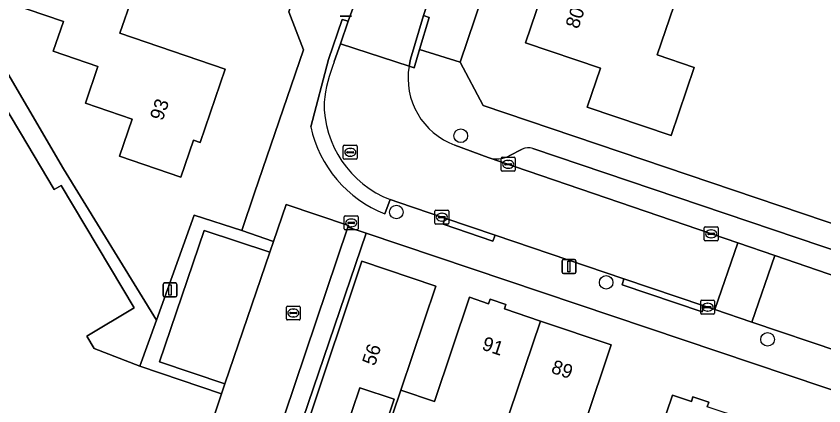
# Model space of a CAD drawing. Extents: x 157767 to 159172, y 387839 to 389425.
# Drawn here: x 158190.5 to 158248.5, y 388348.6 to 388376.5 of the extents above; entities that cross this region are included whole.
import ezdxf

# ---------------------------------------------------------------- set-up
doc = ezdxf.new("R2010")
doc.units = 0
for name, color, linetype in [('IMGEO_Boom', 7, 'Continuous'), ('IMGEO_Brandkraan', 7, 'Continuous'), ('IMGEO_Erf', 7, 'Continuous'), ('IMGEO_Kolk', 7, 'Continuous'), ('IMGEO_Lichtmast', 7, 'Continuous'), ('IMGEO_Pand', 7, 'Continuous'), ('IMGEO_Pand_nummerreeks', 7, 'Continuous'), ('IMGEO_Parkeervlak_open', 7, 'Continuous'), ('IMGEO_Rijbaan_lokaal_open', 7, 'Continuous'), ('IMGEO_Rioolput', 7, 'Continuous'), ('IMGEO_Voetpad_open', 7, 'Continuous')]:
    doc.layers.add(name, color=color, linetype=linetype)

msp = doc.modelspace()

# ---------------------------------------------------------------- linework, layer by layer
at = {"layer": 'IMGEO_Boom'}
for centre in [(158222.451, 388367.952), (158217.826, 388362.477), (158232.884, 388357.425), (158244.465, 388353.331)]:
    msp.add_circle(centre, 0.489, dxfattribs=at)
at = {"layer": 'IMGEO_Brandkraan'}
for p, q in [((158214.085, 388361.271), (158214.085, 388362.123)), ((158214.16, 388362.197), (158215.012, 388362.197)), ((158215.086, 388362.123), (158215.086, 388361.271)), ((158214.344, 388361.691), (158214.344, 388361.703)), ((158214.782, 388361.654), (158214.384, 388361.654)), ((158214.387, 388361.74), (158214.785, 388361.74)), ((158214.573, 388361.977), (158214.598, 388361.977)), ((158214.828, 388361.703), (158214.828, 388361.691)), ((158215.012, 388361.197), (158214.16, 388361.197)), ((158214.596, 388361.417), (158214.571, 388361.417))]:
    msp.add_line(p, q, dxfattribs=at)
for points in [[(158214.085, 388361.271), (158214.085, 388362.123)], [(158214.16, 388362.197), (158215.012, 388362.197)], [(158215.086, 388362.123), (158215.086, 388361.271)], [(158215.012, 388361.197), (158214.16, 388361.197)]]:
    msp.add_lwpolyline(points, dxfattribs=at)
for centre, radius, start, end in [((158214.162, 388362.121), 0.0765, 91.55205, 178.44795), ((158214.162, 388362.121), 0.0765, 91.55205, 178.44795), ((158215.01, 388362.121), 0.0765, 1.55205, 88.44795), ((158215.01, 388362.121), 0.0765, 1.55205, 88.44795), ((158214.384, 388361.7), 0.0403, 85.87752, 175.75265), ((158214.381, 388361.69), 0.0366, 178.93798, 274.71019), ((158214.785, 388361.697), 0.043, 264.86636, 352.45326), ((158214.789, 388361.702), 0.0386, 1.73085, 96.63898), ((158214.162, 388361.273), 0.0765, 181.55205, 268.44795), ((158214.162, 388361.273), 0.0765, 181.55205, 268.44795), ((158215.01, 388361.273), 0.0765, 271.55205, 358.44795), ((158215.01, 388361.273), 0.0765, 271.55205, 358.44795)]:
    msp.add_arc(centre, radius, start, end, dxfattribs=at)
for centre, major_axis, ratio, start_param, end_param in [((158214.572, 388361.697), (-0.387, 0.002), 0.722429, 4.712389, 7.853982), ((158214.597, 388361.697), (-0.39, 0.002), 0.717154, 1.570796, 4.712389)]:
    msp.add_ellipse(centre, major_axis=major_axis, ratio=ratio, start_param=start_param, end_param=end_param, dxfattribs=at)
at = {"layer": 'IMGEO_Erf'}
for points in [[(158227.437, 388427.591), (158206.398, 388461.811), (158193.554, 388453.846), (158183.168, 388447.406), (158182.041, 388442.936), (158182.177, 388442.783), (158184.992, 388444.506), (158185.402, 388443.835), (158188.66, 388445.829), (158190.411, 388442.966), (158187.153, 388440.973), (158188.112, 388439.406), (158185.297, 388437.683), (158197.216, 388418.782), (158193.835, 388409.215), (158175.068, 388397.881), (158178.573, 388391.881), (158193.933, 388365.581), (158200.612, 388354.718), (158203.311, 388362.254), (158206.731, 388361.142), (158207.656, 388363.849), (158211.167, 388374.122), (158210.098, 388376.863)], [(158312.755, 388341.098), (158312.502, 388341.518), (158306.661, 388351.075), (158298.895, 388363.783), (158266.215, 388343.931), (158215.655, 388360.952), (158211.11, 388347.607), (158210.283, 388345.18), (158209.386, 388342.547), (158208.654, 388340.397), (158214.388, 388338.441), (158213.37, 388335.454), (158271.151, 388315.645)]]:
    msp.add_lwpolyline(points, close=True, dxfattribs=at)
for points in [[(158254.733, 388410.921), (158237.149, 388416.834), (158222.397, 388373.231), (158224.063, 388370.135), (158264.935, 388356.284)], [(158204.506, 388347.12), (158205.279, 388349.421), (158199.422, 388351.396), (158196.126, 388352.68), (158195.601, 388353.556), (158199.017, 388355.601), (158193.759, 388364.381), (158193.273, 388364.089), (158190.849, 388368.154), (158181.209, 388384.323)], [(158237.737, 388377.264), (158236.555, 388373.757), (158239.207, 388372.863), (158237.559, 388367.975), (158231.529, 388370.008), (158232.477, 388372.819), (158227.1, 388374.631), (158228.983, 388380.218)], [(158198.86, 388377.879), (158197.988, 388375.331), (158205.547, 388372.742), (158203.744, 388367.476), (158203.257, 388367.643), (158202.348, 388364.986), (158197.958, 388366.489), (158198.867, 388369.145), (158195.504, 388370.297), (158196.408, 388372.938), (158193.199, 388374.037), (158193.928, 388376.164), (158191.323, 388377.056)], [(158211.509, 388347.473), (158215.359, 388358.94), (158220.658, 388357.16), (158218.15, 388349.69), (158220.57, 388348.878), (158223.081, 388356.354), (158224.447, 388355.896), (158224.556, 388356.219), (158225.685, 388355.841), (158225.576, 388355.518), (158228.16, 388354.65), (158233.239, 388352.943), (158231.317, 388347.218)], [(158215.704, 388343.169), (158217.674, 388349.034), (158215.209, 388349.862), (158214.113, 388346.599)], [(158236.359, 388345.525), (158237.638, 388349.335), (158239.004, 388348.877), (158239.113, 388349.2), (158240.242, 388348.822), (158240.132, 388348.497)]]:
    msp.add_lwpolyline(points, dxfattribs=at)
at = {"layer": 'IMGEO_Kolk'}
for p, q in [((158225.349, 388365.48), (158225.349, 388366.332)), ((158225.424, 388366.406), (158226.276, 388366.406)), ((158225.837, 388366.186), (158225.862, 388366.186)), ((158226.35, 388366.332), (158226.35, 388365.48)), ((158225.608, 388365.9), (158225.608, 388365.912)), ((158226.046, 388365.863), (158225.648, 388365.863)), ((158225.651, 388365.949), (158226.049, 388365.949)), ((158225.86, 388365.626), (158225.835, 388365.626)), ((158226.092, 388365.912), (158226.092, 388365.9)), ((158226.276, 388365.406), (158225.424, 388365.406)), ((158220.593, 388361.68), (158220.593, 388362.532)), ((158220.668, 388362.606), (158221.52, 388362.606)), ((158220.852, 388362.1), (158220.852, 388362.112)), ((158220.895, 388362.149), (158221.293, 388362.149)), ((158221.081, 388362.386), (158221.106, 388362.386)), ((158221.336, 388362.112), (158221.336, 388362.1)), ((158221.594, 388362.532), (158221.594, 388361.68)), ((158221.52, 388361.606), (158220.668, 388361.606)), ((158221.29, 388362.063), (158220.892, 388362.063)), ((158221.104, 388361.826), (158221.079, 388361.826)), ((158239.917, 388360.487), (158239.917, 388361.339)), ((158239.992, 388361.413), (158240.844, 388361.413)), ((158240.176, 388360.907), (158240.176, 388360.919)), ((158240.219, 388360.956), (158240.617, 388360.956)), ((158240.405, 388361.193), (158240.43, 388361.193)), ((158240.66, 388360.919), (158240.66, 388360.907)), ((158240.918, 388361.339), (158240.918, 388360.487)), ((158240.844, 388360.413), (158239.992, 388360.413)), ((158240.614, 388360.87), (158240.216, 388360.87)), ((158240.428, 388360.633), (158240.403, 388360.633)), ((158210.005, 388355.724), (158210.857, 388355.724)), ((158239.666, 388355.217), (158239.666, 388356.069)), ((158239.741, 388356.143), (158240.593, 388356.143)), ((158240.154, 388355.923), (158240.179, 388355.923)), ((158240.667, 388356.069), (158240.667, 388355.217)), ((158209.93, 388354.798), (158209.93, 388355.65)), ((158210.189, 388355.218), (158210.189, 388355.23)), ((158210.627, 388355.181), (158210.229, 388355.181)), ((158210.232, 388355.267), (158210.63, 388355.267)), ((158210.418, 388355.504), (158210.443, 388355.504)), ((158210.673, 388355.23), (158210.673, 388355.218)), ((158210.931, 388355.65), (158210.931, 388354.798)), ((158240.593, 388355.143), (158239.741, 388355.143)), ((158239.925, 388355.637), (158239.925, 388355.649)), ((158240.363, 388355.6), (158239.965, 388355.6)), ((158239.968, 388355.686), (158240.366, 388355.686)), ((158240.177, 388355.363), (158240.152, 388355.363)), ((158240.409, 388355.649), (158240.409, 388355.637)), ((158210.857, 388354.724), (158210.005, 388354.724)), ((158210.441, 388354.944), (158210.416, 388354.944))]:
    msp.add_line(p, q, dxfattribs=at)
for points in [[(158225.349, 388365.48), (158225.349, 388366.332)], [(158225.424, 388366.406), (158226.276, 388366.406)], [(158226.35, 388366.332), (158226.35, 388365.48)], [(158226.276, 388365.406), (158225.424, 388365.406)], [(158220.593, 388361.68), (158220.593, 388362.532)], [(158220.668, 388362.606), (158221.52, 388362.606)], [(158221.594, 388362.532), (158221.594, 388361.68)], [(158221.52, 388361.606), (158220.668, 388361.606)], [(158239.917, 388360.487), (158239.917, 388361.339)], [(158239.992, 388361.413), (158240.844, 388361.413)], [(158240.918, 388361.339), (158240.918, 388360.487)], [(158240.844, 388360.413), (158239.992, 388360.413)], [(158210.005, 388355.724), (158210.857, 388355.724)], [(158239.666, 388355.217), (158239.666, 388356.069)], [(158239.741, 388356.143), (158240.593, 388356.143)], [(158240.667, 388356.069), (158240.667, 388355.217)], [(158209.93, 388354.798), (158209.93, 388355.65)], [(158210.931, 388355.65), (158210.931, 388354.798)], [(158240.593, 388355.143), (158239.741, 388355.143)], [(158210.857, 388354.724), (158210.005, 388354.724)]]:
    msp.add_lwpolyline(points, dxfattribs=at)
for centre, radius, start, end in [((158225.426, 388366.33), 0.0765, 91.55205, 178.44795), ((158225.426, 388366.33), 0.0765, 91.55205, 178.44795), ((158226.274, 388366.33), 0.0765, 1.55205, 88.44795), ((158226.274, 388366.33), 0.0765, 1.55205, 88.44795), ((158225.648, 388365.909), 0.0403, 85.87752, 175.75265), ((158225.645, 388365.899), 0.0366, 178.93798, 274.71019), ((158226.049, 388365.906), 0.043, 264.86636, 352.45326), ((158226.053, 388365.911), 0.0386, 1.73085, 96.63898), ((158225.426, 388365.482), 0.0765, 181.55205, 268.44795), ((158225.426, 388365.482), 0.0765, 181.55205, 268.44795), ((158226.274, 388365.482), 0.0765, 271.55205, 358.44795), ((158226.274, 388365.482), 0.0765, 271.55205, 358.44795), ((158220.67, 388362.53), 0.0765, 91.55205, 178.44795), ((158220.67, 388362.53), 0.0765, 91.55205, 178.44795), ((158220.892, 388362.109), 0.0403, 85.87752, 175.75265), ((158220.889, 388362.099), 0.0366, 178.93798, 274.71019), ((158221.293, 388362.106), 0.043, 264.86636, 352.45326), ((158221.297, 388362.111), 0.0386, 1.73085, 96.63898), ((158221.518, 388362.53), 0.0765, 1.55205, 88.44795), ((158221.518, 388362.53), 0.0765, 1.55205, 88.44795), ((158220.67, 388361.682), 0.0765, 181.55205, 268.44795), ((158220.67, 388361.682), 0.0765, 181.55205, 268.44795), ((158221.518, 388361.682), 0.0765, 271.55205, 358.44795), ((158221.518, 388361.682), 0.0765, 271.55205, 358.44795), ((158239.994, 388361.337), 0.0765, 91.55205, 178.44795), ((158239.994, 388361.337), 0.0765, 91.55205, 178.44795), ((158240.216, 388360.916), 0.0403, 85.87752, 175.75265), ((158240.621, 388360.918), 0.0386, 1.73085, 96.63898), ((158240.842, 388361.337), 0.0765, 1.55205, 88.44795), ((158240.842, 388361.337), 0.0765, 1.55205, 88.44795), ((158239.994, 388360.489), 0.0765, 181.55205, 268.44795), ((158239.994, 388360.489), 0.0765, 181.55205, 268.44795), ((158240.213, 388360.906), 0.0366, 178.93798, 274.71019), ((158240.617, 388360.913), 0.043, 264.86636, 352.45326), ((158240.842, 388360.489), 0.0765, 271.55205, 358.44795), ((158240.842, 388360.489), 0.0765, 271.55205, 358.44795), ((158210.007, 388355.648), 0.0765, 91.55205, 178.44795), ((158210.007, 388355.648), 0.0765, 91.55205, 178.44795), ((158210.855, 388355.648), 0.0765, 1.55205, 88.44795), ((158210.855, 388355.648), 0.0765, 1.55205, 88.44795), ((158239.743, 388356.067), 0.0765, 91.55205, 178.44795), ((158239.743, 388356.067), 0.0765, 91.55205, 178.44795), ((158240.591, 388356.067), 0.0765, 1.55205, 88.44795), ((158240.591, 388356.067), 0.0765, 1.55205, 88.44795), ((158210.229, 388355.227), 0.0403, 85.87752, 175.75265), ((158210.226, 388355.217), 0.0366, 178.93798, 274.71019), ((158210.63, 388355.224), 0.043, 264.86636, 352.45326), ((158210.634, 388355.229), 0.0386, 1.73085, 96.63898), ((158239.743, 388355.219), 0.0765, 181.55205, 268.44795), ((158239.743, 388355.219), 0.0765, 181.55205, 268.44795), ((158239.965, 388355.646), 0.0403, 85.87752, 175.75265), ((158239.962, 388355.636), 0.0366, 178.93798, 274.71019), ((158240.366, 388355.643), 0.043, 264.86636, 352.45326), ((158240.37, 388355.648), 0.0386, 1.73085, 96.63898), ((158240.591, 388355.219), 0.0765, 271.55205, 358.44795), ((158240.591, 388355.219), 0.0765, 271.55205, 358.44795), ((158210.007, 388354.8), 0.0765, 181.55205, 268.44795), ((158210.007, 388354.8), 0.0765, 181.55205, 268.44795), ((158210.855, 388354.8), 0.0765, 271.55205, 358.44795), ((158210.855, 388354.8), 0.0765, 271.55205, 358.44795)]:
    msp.add_arc(centre, radius, start, end, dxfattribs=at)
for centre, major_axis, ratio, start_param, end_param in [((158225.836, 388365.906), (-0.387, 0.002), 0.722429, 4.712389, 7.853982), ((158225.861, 388365.906), (-0.39, 0.002), 0.717154, 1.570796, 4.712389), ((158221.08, 388362.106), (-0.387, 0.002), 0.722429, 4.712389, 7.853982), ((158221.105, 388362.106), (-0.39, 0.002), 0.717154, 1.570796, 4.712389), ((158240.404, 388360.913), (-0.387, 0.002), 0.722429, 4.712389, 7.853982), ((158240.429, 388360.913), (-0.39, 0.002), 0.717154, 1.570796, 4.712389), ((158240.153, 388355.643), (-0.387, 0.002), 0.722429, 4.712389, 7.853982), ((158240.178, 388355.643), (-0.39, 0.002), 0.717154, 1.570796, 4.712389), ((158210.417, 388355.224), (-0.387, 0.002), 0.722429, 4.712389, 7.853982), ((158210.442, 388355.224), (-0.39, 0.002), 0.717154, 1.570796, 4.712389)]:
    msp.add_ellipse(centre, major_axis=major_axis, ratio=ratio, start_param=start_param, end_param=end_param, dxfattribs=at)
at = {"layer": 'IMGEO_Lichtmast'}
for p, q in [((158214.594, 388376.546), (158213.804, 388376.546)), ((158213.804, 388376.546), (158214.594, 388376.546)), ((158229.715, 388358.169), (158229.715, 388358.969)), ((158229.715, 388358.969), (158229.715, 388358.169)), ((158229.815, 388359.069), (158230.605, 388359.069)), ((158230.605, 388359.069), (158229.815, 388359.069)), ((158230.705, 388358.969), (158230.705, 388358.169)), ((158230.705, 388358.169), (158230.705, 388358.969)), ((158230.605, 388358.069), (158229.815, 388358.069)), ((158229.815, 388358.069), (158230.605, 388358.069)), ((158201.087, 388356.482), (158201.087, 388357.282)), ((158201.087, 388357.282), (158201.087, 388356.482)), ((158201.187, 388357.382), (158201.977, 388357.382)), ((158201.977, 388357.382), (158201.187, 388357.382)), ((158202.077, 388357.282), (158202.077, 388356.482)), ((158202.077, 388356.482), (158202.077, 388357.282)), ((158201.977, 388356.382), (158201.187, 388356.382)), ((158201.187, 388356.382), (158201.977, 388356.382))]:
    msp.add_line(p, q, dxfattribs=at)
for points in [[(158230.135, 388358.944), (158230.285, 388358.944), (158230.285, 388358.194), (158230.135, 388358.194), (158230.135, 388358.944)], [(158201.507, 388357.257), (158201.657, 388357.257), (158201.657, 388356.507), (158201.507, 388356.507), (158201.507, 388357.257)]]:
    msp.add_lwpolyline(points, dxfattribs=at)
for centre, start, end in [((158229.815, 388358.969), 90, 180), ((158229.815, 388358.969), 90, 180), ((158230.605, 388358.969), 0, 90), ((158230.605, 388358.969), 360, 90), ((158229.815, 388358.169), 180, 270), ((158229.815, 388358.169), 180, 270), ((158230.605, 388358.169), 270, 0), ((158230.605, 388358.169), 270, 0), ((158201.187, 388357.282), 90, 180), ((158201.187, 388357.282), 90, 180), ((158201.977, 388357.282), 0, 90), ((158201.977, 388357.282), 360, 90), ((158201.187, 388356.482), 180, 270), ((158201.187, 388356.482), 180, 270), ((158201.977, 388356.482), 270, 0), ((158201.977, 388356.482), 270, 0)]:
    msp.add_arc(centre, 0.1, start, end, dxfattribs=at)
at = {"layer": 'IMGEO_Pand'}
for points in [[(158205.547, 388372.742), (158197.988, 388375.331), (158198.86, 388377.879), (158192.354, 388380.066), (158189.232, 388381.115), (158188.224, 388378.117), (158191.323, 388377.056), (158193.928, 388376.164), (158193.199, 388374.037), (158196.408, 388372.938), (158195.504, 388370.297), (158198.867, 388369.145), (158197.958, 388366.489), (158202.348, 388364.986), (158203.257, 388367.643), (158203.744, 388367.476)], [(158237.737, 388377.264), (158228.983, 388380.218), (158227.1, 388374.631), (158232.477, 388372.819), (158231.529, 388370.008), (158237.559, 388367.975), (158239.207, 388372.863), (158236.555, 388373.757)], [(158218.15, 388349.69), (158220.658, 388357.16), (158215.359, 388358.94), (158211.509, 388347.473), (158214.113, 388346.599), (158215.209, 388349.862), (158217.674, 388349.034), (158215.704, 388343.169), (158215.924, 388343.095)], [(158228.16, 388354.65), (158225.576, 388355.518), (158225.685, 388355.841), (158224.556, 388356.219), (158224.447, 388355.896), (158223.081, 388356.354), (158220.57, 388348.878), (158218.15, 388349.69), (158215.924, 388343.095), (158218.854, 388342.112), (158219.712, 388344.665), (158221.866, 388343.942), (158224.293, 388343.146), (158225.396, 388346.427)], [(158231.317, 388347.218), (158233.239, 388352.943), (158228.16, 388354.65), (158225.396, 388346.427), (158224.293, 388343.146), (158226.755, 388342.338), (158228.886, 388341.623), (158227.391, 388337.171), (158230.394, 388336.162), (158232.581, 388342.511), (158230.025, 388343.369)], [(158239.945, 388339.407), (158242.743, 388347.62), (158240.132, 388348.497), (158240.242, 388348.822), (158239.113, 388349.2), (158239.004, 388348.877), (158237.638, 388349.335), (158236.359, 388345.525), (158235.066, 388341.676), (158232.581, 388342.511), (158230.394, 388336.162), (158232.131, 388335.579), (158233.349, 388335.17), (158234.207, 388337.726), (158236.36, 388337.004), (158237.448, 388340.245)]]:
    msp.add_lwpolyline(points, close=True, dxfattribs=at)
at = {"layer": 'IMGEO_Parkeervlak_open'}
for points in [[(158226.866, 388366.988), (158225.917, 388366.504)], [(158255.222, 388357.702), (158227.627, 388367.044)], [(158224.424, 388366.393), (158242.328, 388360.257), (158244.986, 388359.346), (158257.232, 388355.149)]]:
    msp.add_lwpolyline(points, dxfattribs=at)
msp.add_lwpolyline([(158205.526, 388350.143), (158208.755, 388359.599), (158204.042, 388361.153), (158200.827, 388351.71)], close=True, dxfattribs=at)
for centre, radius, start, end in [((158227.313, 388366.114), 0.981, 71.33181, 117.08551), ((158225.038, 388368.224), 1.932, 251.45162, 297.05227)]:
    msp.add_arc(centre, radius, start, end, dxfattribs=at)
at = {"layer": 'IMGEO_Rijbaan_lokaal_open'}
for points in [[(158226.272, 388395.851), (158221.586, 388397.439), (158214.694, 388377.106), (158214.372, 388376.178), (158213.812, 388374.563), (158218.733, 388372.942), (158218.845, 388373.452), (158219.775, 388376.603), (158219.991, 388377.243)], [(158214.349, 388361.391), (158214.388, 388361.506), (158209.923, 388363.019), (158209.014, 388360.358), (158208.755, 388359.599), (158205.526, 388350.143), (158205.279, 388349.421), (158204.506, 388347.12), (158209.023, 388345.603)], [(158243.348, 388354.566), (158244.986, 388359.346), (158242.328, 388360.257), (158240.686, 388355.468)]]:
    msp.add_lwpolyline(points, close=True, dxfattribs=at)
for points in [[(158218.733, 388372.942), (158213.812, 388374.563), (158213.365, 388373.277)], [(158217.383, 388363.367), (158218.013, 388363.151), (158221.302, 388362.036), (158224.918, 388360.811), (158234.16, 388357.679), (158239.9, 388355.734), (158240.686, 388355.468), (158242.328, 388360.257), (158224.424, 388366.393), (158222.02, 388367.283)], [(158260.839, 388354.01), (158260.239, 388354.118), (158257.232, 388355.149), (158244.986, 388359.346), (158243.348, 388354.566), (158249.58, 388352.454), (158255.313, 388350.511), (158257.229, 388349.862)]]:
    msp.add_lwpolyline(points, dxfattribs=at)
for centre, radius, start, end in [((158224.347, 388368.977), 11.794, 158.61848, 173.16947), ((158223.798, 388372.1), 5.134, 170.55789, 249.74198), ((158220.123, 388370.333), 7.486, 179.64314, 248.53268)]:
    msp.add_arc(centre, radius, start, end, dxfattribs=at)
at = {"layer": 'IMGEO_Rioolput'}
for p, q in [((158214.017, 388366.343), (158214.017, 388367.195)), ((158214.092, 388367.269), (158214.944, 388367.269)), ((158214.276, 388366.763), (158214.276, 388366.775)), ((158214.714, 388366.726), (158214.316, 388366.726)), ((158214.319, 388366.812), (158214.717, 388366.812)), ((158214.505, 388367.049), (158214.53, 388367.049)), ((158214.76, 388366.775), (158214.76, 388366.763)), ((158215.018, 388367.195), (158215.018, 388366.343)), ((158214.944, 388366.269), (158214.092, 388366.269)), ((158214.528, 388366.489), (158214.503, 388366.489))]:
    msp.add_line(p, q, dxfattribs=at)
for points in [[(158214.017, 388366.343), (158214.017, 388367.195)], [(158214.092, 388367.269), (158214.944, 388367.269)], [(158215.018, 388367.195), (158215.018, 388366.343)], [(158214.944, 388366.269), (158214.092, 388366.269)]]:
    msp.add_lwpolyline(points, dxfattribs=at)
for centre, radius, start, end in [((158214.094, 388367.193), 0.0765, 91.55205, 178.44795), ((158214.094, 388367.193), 0.0765, 91.55205, 178.44795), ((158214.316, 388366.772), 0.0403, 85.87752, 175.75265), ((158214.313, 388366.762), 0.0366, 178.93798, 274.71019), ((158214.717, 388366.769), 0.043, 264.86636, 352.45326), ((158214.721, 388366.774), 0.0386, 1.73085, 96.63898), ((158214.942, 388367.193), 0.0765, 1.55205, 88.44795), ((158214.942, 388367.193), 0.0765, 1.55205, 88.44795), ((158214.094, 388366.345), 0.0765, 181.55205, 268.44795), ((158214.094, 388366.345), 0.0765, 181.55205, 268.44795), ((158214.942, 388366.345), 0.0765, 271.55205, 358.44795), ((158214.942, 388366.345), 0.0765, 271.55205, 358.44795)]:
    msp.add_arc(centre, radius, start, end, dxfattribs=at)
for centre, major_axis, ratio, start_param, end_param in [((158214.504, 388366.769), (-0.387, 0.002), 0.722429, 4.712389, 7.853982), ((158214.529, 388366.769), (-0.39, 0.002), 0.717154, 1.570796, 4.712389)]:
    msp.add_ellipse(centre, major_axis=major_axis, ratio=ratio, start_param=start_param, end_param=end_param, dxfattribs=at)
at = {"layer": 'IMGEO_Voetpad_open'}
for points in [[(158221.808, 388378.155), (158220.32, 388377.493), (158219.991, 388377.243), (158219.775, 388376.603), (158220.185, 388376.459), (158219.494, 388374.153), (158222.397, 388373.231), (158237.149, 388416.834), (158239.61, 388422.451), (158240.217, 388428.536), (158224.669, 388453.69), (158223.359, 388455.784), (158221.068, 388459.446), (158216.064, 388467.448)], [(158206.398, 388461.811), (158227.437, 388427.591), (158210.098, 388376.863), (158211.167, 388374.122), (158207.656, 388363.849), (158206.731, 388361.142), (158209.014, 388360.358), (158209.923, 388363.019), (158214.388, 388361.506), (158214.349, 388361.391), (158215.655, 388360.952), (158266.215, 388343.931)], [(158181.209, 388384.323), (158190.849, 388368.154), (158193.273, 388364.089), (158193.759, 388364.381), (158199.017, 388355.601), (158195.601, 388353.556), (158196.126, 388352.68), (158199.422, 388351.396), (158200.612, 388354.718), (158193.933, 388365.581), (158178.573, 388391.881)], [(158211.676, 388368.603), (158212.957, 388373.437), (158213.939, 388376.3), (158214.372, 388376.178), (158214.694, 388377.106)], [(158213.365, 388373.277), (158213.812, 388374.563), (158214.372, 388376.178), (158213.939, 388376.3), (158212.957, 388373.437), (158211.676, 388368.603)], [(158224.063, 388370.135), (158222.397, 388373.231), (158219.494, 388374.153), (158219.098, 388372.832), (158218.733, 388372.942)], [(158264.935, 388356.284), (158224.063, 388370.135)], [(158222.02, 388367.283), (158224.424, 388366.393)], [(158225.917, 388366.504), (158226.866, 388366.988)], [(158227.627, 388367.044), (158255.222, 388357.702)], [(158217.007, 388362.337), (158217.383, 388363.367)], [(158257.229, 388349.862), (158255.313, 388350.511), (158255.145, 388350.069), (158249.435, 388352.024), (158249.58, 388352.454), (158243.348, 388354.566), (158240.686, 388355.468), (158239.9, 388355.734), (158239.766, 388355.301), (158234.028, 388357.251), (158234.16, 388357.679), (158224.918, 388360.811), (158224.756, 388360.383), (158221.173, 388361.604), (158221.302, 388362.036), (158218.013, 388363.151), (158217.383, 388363.367), (158217.007, 388362.337)]]:
    msp.add_lwpolyline(points, dxfattribs=at)
for points in [[(158220.185, 388376.459), (158219.775, 388376.603), (158218.845, 388373.452), (158218.733, 388372.942), (158219.098, 388372.832), (158219.494, 388374.153)], [(158204.042, 388361.153), (158208.755, 388359.599), (158209.014, 388360.358), (158206.731, 388361.142), (158203.311, 388362.254), (158200.612, 388354.718), (158199.422, 388351.396), (158205.279, 388349.421), (158205.526, 388350.143), (158200.827, 388351.71)], [(158224.918, 388360.811), (158221.302, 388362.036), (158221.173, 388361.604), (158224.756, 388360.383)], [(158211.11, 388347.607), (158215.655, 388360.952), (158214.349, 388361.391), (158209.023, 388345.603), (158210.283, 388345.18)], [(158239.9, 388355.734), (158234.16, 388357.679), (158234.028, 388357.251), (158239.766, 388355.301)]]:
    msp.add_lwpolyline(points, close=True, dxfattribs=at)
for centre, radius, start, end in [((158224.347, 388368.977), 11.794, 158.61848, 173.16947), ((158223.798, 388372.1), 5.134, 170.55789, 249.74198), ((158220.123, 388370.333), 7.486, 179.64314, 248.53268), ((158220.23, 388370.48), 8.758, 192.37637, 248.40471), ((158220.23, 388370.48), 8.758, 192.37637, 248.40471), ((158227.313, 388366.114), 0.981, 71.33181, 117.08551), ((158225.038, 388368.224), 1.932, 251.45162, 297.05227)]:
    msp.add_arc(centre, radius, start, end, dxfattribs=at)

# ---------------------------------------------------------------- texts
at = {"layer": 'IMGEO_Pand_nummerreeks'}
for s, rotation, p in [('80', 71.37328, (158230.881, 388375.578)), ('93', 71.10406, (158201.051, 388368.982)), ('91', 341.43617, (158223.899, 388352.618)), ('56', 71.44073, (158216.28, 388351.378)), ('89', 341.43617, (158228.871, 388350.949))]:
    msp.add_text(s, height=1, rotation=rotation, dxfattribs=at).set_placement(p)

doc.saveas('drawing.dxf')
